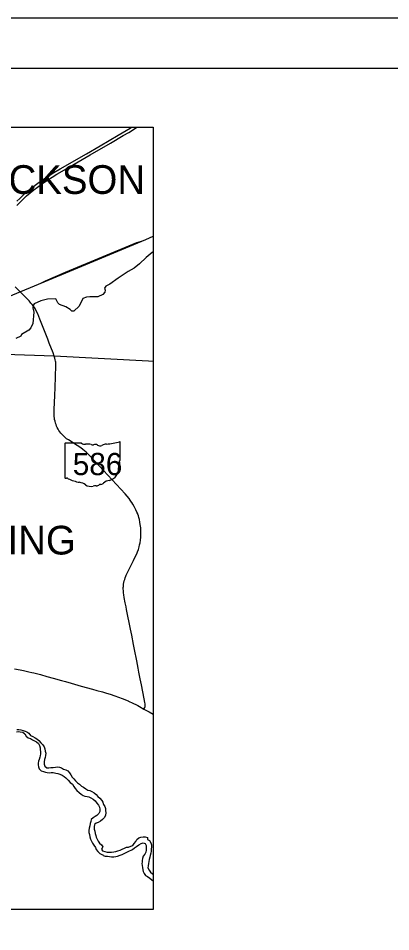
# Model space of a CAD drawing. Extents: x 0 to 34, y 0 to 22.
# Drawn here: x 17.72 to 21.45, y 12.85 to 22 of the extents above; entities that cross this region are included whole.
import ezdxf

# ---------------------------------------------------------------- set-up
doc = ezdxf.new("R2010")
doc.units = 0
for name, color, linetype in [('GM_X_Major_River', 7, 'Continuous'), ('GM_X_Minor_River', 7, 'Continuous'), ('GM_X_Rail_Line', 7, 'Continuous'), ('GM_X_State_Route', 7, 'Continuous'), ('GM_X_State_Shield', 7, 'Continuous'), ('GM_X_Township', 7, 'Continuous'), ('GM_X_Township_Text', 7, 'Continuous'), ('SH_Border', 7, 'Continuous'), ('SH_Cut_Line', 7, 'Continuous'), ('SH_Text', 7, 'Continuous')]:
    doc.layers.add(name, color=color, linetype=linetype)

msp = doc.modelspace()

# ---------------------------------------------------------------- linework, layer by layer
at = {"layer": 'GM_X_Major_River'}
for points in [[(17.6976, 14.8482), (17.7177, 14.8502), (17.7358, 14.8487), (17.7608, 14.8445), (17.7814, 14.8274), (17.793, 14.8051), (17.8136, 14.7879), (17.8366, 14.781), (17.8577, 14.7695), (17.8782, 14.7588), (17.8981, 14.7486), (17.9173, 14.7327), (17.9283, 14.711), (17.9341, 14.6886), (17.9342, 14.6707), (17.9387, 14.6496), (17.9388, 14.6291), (17.9351, 14.6093), (17.9313, 14.5933), (17.925, 14.5715), (17.9193, 14.5555), (17.9137, 14.5343), (17.9144, 14.5183), (17.917, 14.4979), (17.9254, 14.4774), (17.9459, 14.459), (17.967, 14.4501), (17.9882, 14.4451), (18.0048, 14.4407), (18.0265, 14.4388), (18.0457, 14.4421), (18.0655, 14.4416), (18.0898, 14.4359), (18.1103, 14.4315), (18.1327, 14.4259), (18.1538, 14.4157), (18.1762, 14.4005), (18.1923, 14.3865), (18.2134, 14.3654), (18.2346, 14.3418), (18.2583, 14.3228), (18.2731, 14.3017), (18.2866, 14.2794), (18.3033, 14.2596), (18.3245, 14.2405), (18.3444, 14.2252), (18.3655, 14.2106), (18.3815, 14.2043), (18.4039, 14.2012), (18.4206, 14.1955), (18.4429, 14.1879), (18.4641, 14.1746), (18.4846, 14.1555), (18.502, 14.1351), (18.5187, 14.114), (18.5296, 14.0936), (18.5329, 14.0731), (18.5317, 14.0514), (18.5216, 14.0302), (18.5018, 14.009), (18.4853, 13.9987), (18.4642, 13.9864), (18.4438, 13.9704), (18.442, 13.9505), (18.437, 13.9287), (18.4307, 13.905), (18.425, 13.8833), (18.4226, 13.8608), (18.4227, 13.8391), (18.4272, 13.818), (18.4318, 13.795), (18.4383, 13.7739), (18.4498, 13.7541), (18.4582, 13.733)], [(17.6995, 14.8706), (17.7199, 14.8732), (17.741, 14.8669), (17.7628, 14.8625), (17.7852, 14.855), (17.8012, 14.8499), (17.8217, 14.834), (17.8377, 14.813), (17.8614, 14.8003), (17.8845, 14.7869), (17.9011, 14.7787), (17.9217, 14.7615), (17.9409, 14.7386), (17.9608, 14.7188), (17.9731, 14.6977), (17.9827, 14.6773), (17.9847, 14.6549), (17.9899, 14.6332), (17.9881, 14.6102), (17.9831, 14.5897), (17.9781, 14.5704), (17.9743, 14.548), (17.9731, 14.525), (17.9803, 14.5033), (18.0008, 14.4886), (18.0212, 14.4881), (18.0423, 14.4894), (18.064, 14.4902), (18.087, 14.4935), (18.1094, 14.4974), (18.1292, 14.493), (18.149, 14.4867), (18.1695, 14.4759), (18.1919, 14.4684), (18.2118, 14.4576), (18.2291, 14.4365), (18.2426, 14.4161), (18.2536, 14.395), (18.2709, 14.3778), (18.2876, 14.3581), (18.3081, 14.3383), (18.3286, 14.3237), (18.3485, 14.3046), (18.369, 14.2925), (18.3908, 14.276), (18.4126, 14.2639), (18.4324, 14.2595), (18.4529, 14.2513), (18.4747, 14.238), (18.4946, 14.2201), (18.5119, 14.2004), (18.5318, 14.1825), (18.5511, 14.1615), (18.562, 14.1436), (18.5704, 14.1194), (18.5826, 14.0989), (18.5904, 14.0791), (18.5905, 14.0587), (18.5925, 14.0363), (18.5881, 14.0119), (18.5799, 13.9889), (18.5595, 13.9683), (18.5379, 13.9516), (18.5168, 13.94), (18.4958, 13.9341), (18.4779, 13.9187), (18.4742, 13.8969), (18.4756, 13.8745), (18.4808, 13.8528)], [(18.4808, 13.8528), (18.486, 13.8304), (18.4905, 13.8093), (18.4963, 13.7927), (18.5066, 13.7723), (18.517, 13.7525), (18.5298, 13.7327), (18.5497, 13.7155), (18.5619, 13.6951), (18.5505, 13.6733), (18.5583, 13.6554), (18.5813, 13.6485), (18.6043, 13.6441), (18.6261, 13.641), (18.6491, 13.6424), (18.6721, 13.6444), (18.6918, 13.6502), (18.7129, 13.6567), (18.7359, 13.6626), (18.755, 13.6735), (18.778, 13.6832), (18.799, 13.6923), (18.8195, 13.693), (18.8424, 13.7021), (18.8616, 13.7105), (18.8775, 13.7298), (18.8921, 13.749), (18.9035, 13.7689), (18.9226, 13.7869), (18.9443, 13.7934), (18.9654, 13.796), (18.9871, 13.7968), (19.0082, 13.7911), (19.0109, 13.7694), (19.0301, 13.7579), (19.043, 13.7375), (19.0488, 13.7171), (19.0502, 13.6947), (19.0477, 13.6742), (19.0459, 13.6524), (19.0434, 13.6313), (19.0371, 13.6089), (19.0333, 13.5922), (19.0277, 13.5704), (19.0239, 13.55), (19.0189, 13.5288), (19.0152, 13.5058), (19.0146, 13.484), (19.0262, 13.4623), (19.0384, 13.4406), (19.0596, 13.426), (19.068, 13.4233)], [(18.4582, 13.733), (18.4737, 13.7113), (18.4872, 13.6903), (18.4956, 13.6705), (18.511, 13.6494), (18.5315, 13.6297), (18.552, 13.6208), (18.5622, 13.617)], [(18.5622, 13.617), (18.5655, 13.61), (18.5853, 13.6031), (18.6077, 13.6019), (18.6294, 13.5994), (18.6499, 13.5969), (18.6716, 13.5951), (18.6914, 13.5978), (18.708, 13.6017), (18.7348, 13.6133), (18.7559, 13.6198), (18.7763, 13.6282), (18.8171, 13.6476), (18.8592, 13.6708), (18.8802, 13.6869), (18.9, 13.6991), (18.9235, 13.7159), (18.9465, 13.7281), (18.9656, 13.7346), (18.9874, 13.7309), (18.9964, 13.7085), (18.9978, 13.6861), (18.9966, 13.6624), (18.9941, 13.6426), (18.9815, 13.6214), (18.9668, 13.6009), (18.9586, 13.5804), (18.9574, 13.5593), (18.9549, 13.5433), (18.9544, 13.5273), (18.957, 13.5081), (18.959, 13.4876), (18.9623, 13.4659), (18.9655, 13.4492), (18.9765, 13.4288), (18.9913, 13.409), (19.0111, 13.397), (19.0316, 13.3817), (19.0534, 13.3665), (19.068, 13.3552)]]:
    msp.add_lwpolyline(points, dxfattribs=at)
at = {"layer": 'GM_X_Minor_River'}
for points in [[(19.068, 19.6639), (19.056, 19.6532), (18.9948, 19.6037), (18.9304, 19.5395), (18.8756, 19.4958), (18.8168, 19.4636), (18.7167, 19.3942), (18.6337, 19.3363), (18.591, 19.3144), (18.5795, 19.2965), (18.5853, 19.2766), (18.5835, 19.2542), (18.5631, 19.2311), (18.5133, 19.2098), (18.4506, 19.209), (18.4334, 19.2083), (18.3995, 19.205), (18.3618, 19.1927), (18.3256, 19.1151), (18.2708, 19.0644), (18.2522, 19.0637), (18.2343, 19.0816), (18.1913, 19.1096), (18.1273, 19.1305), (18.11, 19.1477), (18.09, 19.188), (18.0095, 19.1833), (17.9418, 19.1696), (17.8747, 19.1387), (17.8639, 19.1201), (17.8608, 19.0977), (17.8699, 19.0561), (17.8626, 18.9421), (17.8416, 18.8985), (17.8225, 18.8754), (17.7491, 18.8317)], [(17.7491, 18.8317), (17.7409, 18.8156), (17.6917, 18.7892)]]:
    msp.add_lwpolyline(points, dxfattribs=at)
at = {"layer": 'GM_X_Rail_Line'}
for points in [[(15.9608, 18.5184), (17.1741, 19.0245), (17.5653, 19.1881), (18.1909, 19.4493), (18.992, 19.7843), (19.068, 19.816)], [(17.9478, 19.3478), (17.9871, 19.3694), (18.1891, 19.4538), (18.9028, 19.7522), (18.9502, 19.7668)]]:
    msp.add_lwpolyline(points, dxfattribs=at)
at = {"layer": 'GM_X_State_Route'}
for points in [[(17.6998, 20.1661), (17.7298, 20.1953), (17.7642, 20.2275), (17.7956, 20.2552), (17.8317, 20.2856), (17.8725, 20.3184), (17.9101, 20.3469), (17.9441, 20.3713), (17.9788, 20.3947), (18.0141, 20.4173), (18.0723, 20.4527), (18.1356, 20.4899), (18.3985, 20.6427), (18.5342, 20.7221), (18.7156, 20.8272), (18.7971, 20.8749), (18.8374, 20.8995), (18.8489, 20.907)], [(17.7005, 20.1249), (17.7377, 20.1618), (17.772, 20.1943), (17.7992, 20.219), (17.835, 20.2497), (17.8715, 20.2797), (17.9089, 20.3086), (17.9469, 20.3365), (17.977, 20.3576), (18.012, 20.3809), (18.0563, 20.4089), (18.1013, 20.4359), (18.1784, 20.4806), (18.3141, 20.56), (18.4367, 20.6308), (18.6405, 20.7495), (18.7673, 20.8235), (18.8214, 20.8555), (18.8704, 20.8858), (18.9027, 20.907)], [(18.0838, 18.288), (18.0889, 18.4162), (18.0918, 18.5094), (18.0919, 18.526), (18.091, 18.5423), (18.09, 18.5533), (18.0887, 18.5632), (18.086, 18.5782), (18.0821, 18.5935), (18.0759, 18.6135), (18.0635, 18.6481), (18.0263, 18.7449), (18.0106, 18.7837), (17.9322, 18.9833), (17.9207, 19.0124), (17.9104, 19.0364), (17.8992, 19.06), (17.887, 19.0831), (17.8763, 19.101), (17.8669, 19.1142), (17.8547, 19.1307), (17.8425, 19.1456), (17.8341, 19.1556), (17.8242, 19.1666), (17.685, 19.3076)], [(18.9744, 15.0773), (18.9824, 15.0939), (18.9851, 15.1023), (18.9854, 15.1079), (18.9854, 15.1183), (18.9847, 15.1286), (18.9826, 15.144), (18.9759, 15.1799), (18.9484, 15.3184), (18.9366, 15.3801), (18.9235, 15.4468), (18.9154, 15.4878), (18.9019, 15.5598), (18.8803, 15.6728), (18.8702, 15.7241), (18.8515, 15.8163), (18.8394, 15.8779), (18.8008, 16.0732), (18.7956, 16.1016), (18.7873, 16.1427), (18.7774, 16.1942), (18.7729, 16.2201), (18.7698, 16.241), (18.7695, 16.2456), (18.7682, 16.2616), (18.7671, 16.2819), (18.7671, 16.2948), (18.7678, 16.3055), (18.7686, 16.3159), (18.7705, 16.329), (18.7737, 16.3459), (18.7772, 16.3613), (18.7813, 16.3768), (18.7867, 16.3922), (18.7923, 16.4072), (18.7971, 16.4187), (18.8127, 16.4522), (18.8256, 16.4775), (18.8704, 16.5664), (18.8843, 16.5946), (18.9015, 16.6328), (18.9094, 16.6522), (18.9181, 16.6768), (18.9257, 16.7018), (18.9309, 16.7221), (18.9351, 16.7426), (18.9392, 16.7685), (18.9425, 16.7996), (18.9436, 16.8209), (18.944, 16.8415), (18.9436, 16.8621), (18.9414, 16.8936), (18.9376, 16.9248), (18.9335, 16.9506), (18.9285, 16.9763), (18.9237, 16.9967), (18.9192, 17.0117), (18.9121, 17.0313), (18.9117, 17.0323), (18.9039, 17.0505), (18.8927, 17.0742), (18.8759, 17.1068), (18.863, 17.1296), (18.8519, 17.1474), (18.8491, 17.1518), (18.8373, 17.169), (18.8248, 17.1858), (18.805, 17.2102), (18.7845, 17.234), (18.5251, 17.5157), (18.4893, 17.5541), (18.4319, 17.6154), (18.4062, 17.6415), (18.3948, 17.6523), (18.379, 17.666), (18.3626, 17.679), (18.3414, 17.6942), (18.3065, 17.7175), (18.2176, 17.7743), (18.1999, 17.7863), (18.1833, 17.7996), (18.1714, 17.8105), (18.1614, 17.8205), (18.1568, 17.8253), (18.1508, 17.8317), (18.1402, 17.8433), (18.1306, 17.8558), (18.1217, 17.8691), (18.1132, 17.8833), (18.1061, 17.8979), (18.0996, 17.9123), (18.0939, 17.9271), (18.0888, 17.9421), (18.0832, 17.9624), (18.0797, 17.9778), (18.0784, 17.9856), (18.077, 17.9934), (18.0753, 18.0092), (18.0745, 18.025), (18.0757, 18.0897), (18.0777, 18.1404), (18.0812, 18.2295), (18.0838, 18.288)], [(17.6758, 15.4784), (17.7328, 15.4695), (17.769, 15.4628), (17.8202, 15.4515), (17.851, 15.4441), (17.8712, 15.4393), (17.937, 15.4215), (18.0028, 15.4035), (18.0634, 15.3864), (18.1493, 15.3627), (18.1894, 15.3515), (18.2453, 15.3359), (18.3464, 15.3077), (18.4576, 15.2769), (18.5031, 15.2641), (18.5586, 15.2484), (18.599, 15.2371), (18.6342, 15.2266), (18.6839, 15.2098), (18.7184, 15.1973), (18.7574, 15.1818), (18.8156, 15.1577), (18.82, 15.1557), (18.8633, 15.1359), (18.901, 15.1175), (18.9127, 15.1113), (18.9289, 15.1028), (18.9744, 15.0773)], [(18.9744, 15.0773), (19.0272, 15.0482), (19.068, 15.0245)]]:
    msp.add_lwpolyline(points, dxfattribs=at)
at = {"layer": 'GM_X_State_Shield'}
for p, q in [((18.181, 17.7352), (18.181, 17.3975)), ((18.3494, 17.741), (18.1865, 17.741)), ((18.7372, 17.5727), (18.7372, 17.7493)), ((18.7372, 17.5727), (18.7372, 17.5727))]:
    msp.add_line(p, q, dxfattribs=at)
for centre, major_axis, start_param, end_param in [((18.1874, 17.7359), (0.00644, 0), 1.712693, 3.28349), ((18.3882, 17.7802), (0.0625, 0), 4.042523, 4.731795), ((18.4089, 17.5514), (0.2244, 0), 1.404758, 1.657858), ((18.4598, 17.7376), (0.018, 0), 3.836095, 5.185415), ((18.4863, 17.6986), (0.0375, 0), 0.950623, 2.079405), ((18.5347, 17.7521), (0.0451, 0), 4.081561, 5.145723), ((18.6143, 17.6378), (0.1187, 0), 1.699011, 2.107814), ((18.5391, 18.2014), (0.5898, 0), 4.814394, 5.042369), ((18.731, 17.7501), (0.00619, 0), 6.141152, 7.989035), ((18.5721, 17.4763), (0.1475, 0), 5.101752, 6.440018), ((18.7594, 17.4988), (0.0418, 0), 2.387724, 3.262537), ((18.7358, 17.5597), (0.00958, 0), 1.883978, 3.671073), ((18.6748, 17.5374), (0.0575, 0), 5.934695, 6.695948), ((18.7306, 17.572), (0.00663, 0), 5.05454, 6.418171), ((18.1875, 17.3967), (0.0065, 0), 3.00124, 4.508301), ((18.1885, 17.4313), (0.0496, 0), 4.665946, 4.897461), ((18.1986, 17.378), (0.0179, 0), 0.519207, 1.627899), ((18.4244, 17.6814), (0.4259, 0), 4.195997, 4.488961), ((18.2975, 17.2457), (0.1333, 0), 0.823519, 1.323587), ((18.4416, 17.3763), (0.0846, 0), 4.026481, 4.996735), ((18.4904, 17.2595), (0.0695, 0), 1.495662, 1.94098), ((18.4966, 17.351), (0.0451, 0), 4.691044, 5.507374), ((18.5374, 17.3183), (0.0127, 0), 1.147584, 2.315152), ((18.532, 17.3647), (0.0477, 0), 4.937069, 5.64225), ((18.6343, 17.3026), (0.0808, 0), 1.647645, 2.488434)]:
    msp.add_ellipse(centre, major_axis=major_axis, ratio=0.8, start_param=start_param, end_param=end_param, dxfattribs=at)
at = {"layer": 'GM_X_Township'}
msp.add_lwpolyline([(19.068, 18.5614), (19.021, 18.563), (18.0755, 18.6144), (16.194, 18.6785), (16.1711, 18.6793), (16.0838, 18.6828), (15.9755, 18.686)], dxfattribs=at)
at = {"layer": 'SH_Border'}
msp.add_lwpolyline([(1.5, 21.5), (33.5, 21.5), (33.5, 0.5), (1.5, 0.5)], close=True, dxfattribs=at)
at = {"layer": 'SH_Cut_Line'}
msp.add_lwpolyline([(0, 0), (34, 0), (34, 22), (0, 22)], close=True, dxfattribs=at)
at = {"layer": 'SH_Text'}
msp.add_lwpolyline([(1.9289, 20.907), (19.068, 20.907), (19.068, 13.067), (1.9289, 13.067)], close=True, dxfattribs=at)

# ---------------------------------------------------------------- texts
at = {"layer": 'GM_X_State_Shield'}
msp.add_text('586', height=0.22247, dxfattribs=at).set_placement((18.2611, 17.4213))
at = {"layer": 'GM_X_Township_Text'}
for s, p in [('JACKSON', (17.1688, 20.2398)), ('LICKING', (16.7525, 16.6259))]:
    msp.add_text(s, height=0.28764, rotation=0.00001, dxfattribs=at).set_placement(p)

doc.saveas('drawing.dxf')
